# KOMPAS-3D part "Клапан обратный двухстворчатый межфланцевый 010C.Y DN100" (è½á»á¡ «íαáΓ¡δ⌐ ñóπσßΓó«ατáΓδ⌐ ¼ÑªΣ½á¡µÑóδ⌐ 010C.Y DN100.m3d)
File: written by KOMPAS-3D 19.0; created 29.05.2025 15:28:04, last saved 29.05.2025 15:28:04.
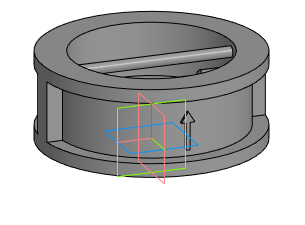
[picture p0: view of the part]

Document properties: Полное имя файла: E:\Dendor Работа Сачек\3D для проекитирвщиков\5.2 Тип 010C, 010C.Y Клапан обратный двухстворчатый межфланцевый\stp_Клапан обратный двухстворчатый межфланцевый 010C.Y\Клапан обратный двухстворчатый межфланцевый 010C.Y DN100.m3d

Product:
- Part/product: Клапан обратный двухстворчатый межфланцевый 010C.Y DN100

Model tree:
1. Операция без истории:1  (labels: Клапан обратный двухстворчатый межфланцевый 010C.Y DN100)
